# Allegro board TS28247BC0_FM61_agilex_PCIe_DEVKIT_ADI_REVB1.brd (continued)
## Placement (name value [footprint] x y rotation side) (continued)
C1846  470uF  [CAPMP7343X300L130X240N_P079IN]  165.74 35.46 180 top
C1847  470uF  [CAPMP7343X300L130X240N_P079IN]  174.87 62.18 0 top
C1848  1u  [CAPC1005X60L20L]  186.42 65.59 270 top
C1849  1u  [CAPC1005X60L20L]  186.52 75.97 270 top
C1850  22u  [CAPC3216X135L50N]  193.4 77.83 180 bottom
C1851  22u  [CAPC3216X135L50N]  193.4 77.83 180 top
C1852  22u  [CAPC3216X135L50N]  185.66 64.04 0 top
C1853  22u  [CAPC3216X135L50N]  185.68 64.04 0 bottom
C1856  470uF  [CAPMP7343X300L130X240N_P079IN]  165.49 69.29 180 top
C1857  100u  [CAPC2012X110L50L]  175.52 70.39 90 bottom
C1858  100u  [CAPC2012X110L50L]  175.52 68.38 90 bottom
C1859  1u  [CAPC1005X60L20L]  186.49 60.3 270 top
C1860  1u  [CAPC1005X60L20L]  186.47 49.91 270 top
C1861  22u  [CAPC3216X135L50N]  185.66 61.85 0 bottom
C1862  22u  [CAPC3216X135L50N]  185.66 61.85 0 top
C1863  22u  [CAPC3216X135L50N]  185.76 48.19 0 top
C1864  22u  [CAPC3216X135L50N]  185.76 48.19 0 bottom
C1867  22uF  [1206]  197.29 46.31 180 bottom
C1868  0.1uF  [0402]  196.1 49.61 180 top
C1869  470uF  [CAPMP7343X300L130X240N_P079IN]  165.49 54.87 180 top
C1870  100u  [CAPC2012X110L50L]  175.52 55.96 90 bottom
C1871  100u  [CAPC2012X110L50L]  175.52 53.95 90 bottom
C1872  22uF  [1206]  194.29 50.62 90 bottom
C1873  1uF  [0402]  198.64 51.13 45 top
C1874  10nF  [0402]  196.48 51.51 90 top
C1875  1u  [CAPC1005X60L20L]  186.67 33.76 270 top
C1876  1u  [CAPC1005X60L20L]  186.57 44.12 270 top
C1877  22u  [CAPC3216X135L50N]  185.81 45.54 0 bottom
C1878  22u  [CAPC3216X135L50N]  185.81 45.7 0 top
C1879  22u  [CAPC3216X135L50N]  191.55 34.09 180 top
C1880  22u  [CAPC3216X135L50N]  191.55 33.91 180 bottom
C1883  470uF  [CAPMP7343X300L130X240N_P079IN]  165.74 40.26 180 top
C1884  100u  [CAPC2012X110L50L]  175.52 40.92 90 bottom
C1885  100u  [CAPC2012X110L50L]  175.52 38.92 90 bottom
C1886  470uF  [D2E]  217.3 48.34 90 top
C1887  100uF  [1206]  215.88 48.47 270 bottom
C1888  100uF  [1206]  218.07 48.47 270 bottom
C1889  100uF  [1206]  220.25 48.47 270 bottom
C1890  220 uF  [CT7361-20]  218.14 57.43 270 bottom
C1891  22uF  [1206]  227.21 61.17 0 bottom
C1892  22uF  [1206]  227.21 61.17 0 top
C1893  22uF  [1206]  234.45 61.04 180 bottom
C1894  22uF  [1206]  234.45 61.17 180 top
C1895  1uF  [0402]  229.01 56.92 0 bottom
C1896  100uF  [1206]  237.5 42.75 90 bottom
C1897  100uF  [1206]  239.68 42.75 90 bottom
C1898  100uF  [1206]  241.87 42.75 90 bottom
C1899  470uF  [D2E]  241.82 42.37 270 top
C1900  1uF  [0402]  211.18 58.3 0 bottom
C1901  1uF  [0402]  209.3 61.8 270 bottom
C1902  22pF  [0402]  205.47 55.68 270 bottom
C1903  22uF  [1206]  209.96 63.48 0 top
C1904  10nF  [0402]  205.7 56.95 270 bottom
C1905  47uF  [C1206]  214.59 55.55 270 top
C1906  47uF  [C1206]  214.59 60.25 90 top
C1907  100uF  [1206]  64.9 64.09 180 top
C1908  22uF  [1206]  64.9 64.09 180 bottom
C1909  100pF  [0402]  72.42 71.55 90 bottom
C1910  22uF  [0603]  72.85 73.92 0 bottom
C1911  22uF  [0603]  76.89 70.31 180 bottom
C1912  47uF  [1206]  72.65 77.55 180 top
C1913  100uF  [1206]  72.65 77.55 0 bottom
C1914  0.1uF,DNI  [0402]  232.29 75.64 0 bottom
C1915  100uF  [1206]  219.84 81.99 0 top
C1916  100uF  [1206]  226.07 81.99 180 bottom
C1917  100uF  [1206]  219.84 81.99 0 bottom
C1918  150uF  [7343P]  236.91 81.16 90 bottom
C1919  22uF  [1206]  236.86 68.25 180 bottom
C1920  22uF  [1206]  236.86 68.3 180 top
C1921  22uF  [1206]  236.86 65.99 180 bottom
C1922  22uF  [1206]  236.86 66.12 180 top
C1923  22uF  [1206]  236.86 63.76 180 bottom
C1924  22uF  [1206]  236.86 63.83 180 top
C1925  10uF  [1206]  236.86 70.51 180 bottom
C1926  100uF,DNI  [1206]  224.8 78.18 180 bottom
C1928  470uF  [2917]  230.26 85.55 0 top
C1929  470uF  [2917]  220.73 85.55 180 top
C1930  100uF  [1206]  220.99 63.35 0 bottom
C1931  100uF  [1206]  225.69 63.35 180 bottom
C1932  100uF  [1206]  226.07 81.99 180 top
C1933  0.1uF,DNI  [0402]  219.08 78.82 90 bottom
C1934  2.2uF  [0402]  225.31 69.98 270 bottom
C1935  1500pF  [0402]  222.54 74.73 225 bottom
C1940  150pF  [0402]  221.57 73.23 180 bottom
C1941  100uF  [1206]  61.68 58.78 270 bottom
C1942  22uF  [1206]  63.15 52.05 180 bottom
C1943  100pF  [0402]  72.12 57.74 90 bottom
C1944  22uF  [0603]  72.8 60.07 0 bottom
C1945  22uF  [0603]  76.87 56.47 180 bottom
C1946  47uF  [1206]  72.78 63.96 180 bottom
C1947  100uF  [1206]  72.78 63.96 0 top
C1948  22uF  [1206]  197.62 83.01 270 bottom
C1949  22uF  [1206]  197.62 83.01 270 top
C1950  1u  [CAPC1005X60L20L]  201.43 83.9 90 bottom
C1951  2.2uF  [CC0603N]  212.99 80.09 0 bottom
C1952  100uF  [1206]  199.85 76.99 0 bottom
C1953  100uF  [1206]  204.68 76.99 180 bottom
C1954  100uF  [1206]  212.73 76.91 180 top
C1956  0.1uF,DNI  [0402]  203.66 86.13 45 bottom
C1957  0.1uF  [0402]  200.79 85.8 0 bottom
C1958  22uF  [1206]  196.22 40.36 270 bottom
C1959  22uF  [1206]  195.82 37.24 90 top
C1960  1u  [CAPC1005X60L20L]  199.78 41.2 90 bottom
C1961  2.2uF  [CC0603N]  197.62 36.15 180 bottom
C1962  100uF  [1206]  199.14 34.11 0 top
C1963  100uF  [1206]  208.92 34.14 0 top
C1964  100uF  [1206]  203.94 34.11 180 top
C1966  0.1uF,DNI  [0402]  206.41 46.56 0 bottom
C1967  0.1uF  [0402]  198.64 43.77 270 bottom
C1975  1uF  [0402]  210.65 70.44 180 top
C1976  1uF  [0402]  212.94 71.53 225 top
C1977  22uF  [1206]  212 74.58 180 bottom
C1978  22pF  [0402]  215.2 65.28 180 top
C1979  10nF  [0402]  215.78 67.39 180 top
C1980  47uF  [C1206]  205.84 68.23 180 bottom
C1981  47uF  [C1206]  205.84 66.04 180 bottom
C1986  22uF  [1206]  70.62 43.89 180 top
C1987  1u  [CAPC1005X60L20L]  68.66 36.73 90 bottom
C1988  47uF  [C1206]  64.09 35.74 270 top
C1989  47uF  [C1206]  74.76 42.52 90 top
C1990  1uF  [0402]  54.13 54.28 90 top
C1991  22uF  [1206]  48.6 55.43 0 bottom
C1992  47uF  [C1206]  49.84 59.11 90 bottom
C1993  47uF  [C1206]  48.62 52.98 0 bottom
C1994  1uF  [0402]  190.58 69.9 180 bottom
C1995  10uF  [0402]  188.75 69.04 0 bottom
C1996  1uF  [0402]  190.45 54.89 180 bottom
C1997  10uF  [0402]  188.53 54.46 0 bottom
C1998  1uF  [0402]  190.43 38.61 180 bottom
C1999  10uF  [0402]  188.5 38.28 0 bottom
C2000  22uF  [1206]  209.96 63.48 0 bottom
C2001  22uF  [1206]  212 74.58 180 top
C2002  1uF  [0402]  236.61 59.13 180 bottom
C2003  DNI  [0402]  231.55 52.63 0 bottom
C2004  360pF  [0402]  232.85 53.65 90 bottom
C2007  0.47uF  [0402]  192.84 63.63 270 bottom
C2008  0.47uF  [0402]  197.17 66.59 180 bottom
C2009  0.47uF  [0402]  192.86 64.54 270 bottom
C2010  0.47uF  [0402]  195.47 66.51 180 bottom
C2011  22u  [CAPC3216X135L50N]  200.34 68.46 0 bottom
C2012  0.1uF,DNI  [0402]  195.43 59.87 180 bottom
C2013  100u  [CAPC2012X110L50L]  175.52 86.62 90 bottom
C2014  100u  [CAPC2012X110L50L]  175.52 80.34 90 bottom
C2015  100u  [CAPC2012X110L50L]  175.52 66.37 90 bottom
C2016  100u  [CAPC2012X110L50L]  175.52 72.39 90 bottom
C2017  47pF  [0402]  189.5 80.1 0 bottom
C2018  47pF  [0402]  188.65 87.99 0 bottom
C2019  47pF  [0402]  190.1 74.7 270 bottom
C2020  47pF  [0402]  189.47 65.94 0 bottom
C2021  100u  [CAPC2012X110L50L]  175.52 57.86 90 bottom
C2022  100u  [CAPC2012X110L50L]  175.52 52.02 90 bottom
C2023  100u  [CAPC2012X110L50L]  175.52 36.91 90 bottom
C2024  100u  [CAPC2012X110L50L]  175.52 42.93 90 bottom
C2025  47pF  [0402]  188.65 59.79 0 bottom
C2026  47pF  [0402]  189.24 50.42 0 bottom
C2027  47pF  [0402]  188.5 43.49 0 bottom
C2028  47pF  [0402]  190.1 36.73 90 bottom
C2029  22uF  [1206]  192.01 46.38 0 bottom
C2030  22uF  [1206]  205.06 49.99 90 bottom
C2031  100pF,DNI  [0402]  196.54 52.78 270 top
C2032  100pF,DNI  [0402]  209.02 54.94 270 bottom
C2033  100pF,DNI  [0402]  212.71 65.28 180 top
C2034  100pF  [0402]  64.19 43.79 90 bottom
C2035  22uF  [1206]  68.76 34.45 0 top
C2036  100pF  [0402]  59.14 56.54 0 top
C2037  22uF  [1206]  48.6 55.43 0 top
C2038  4.7uF  [0402]  52.48 54.74 45 top
C2039  4.7uF  [0402]  71.1 40.39 225 bottom
C7761  0.1uF  [0402]  230.82 19.64 0 top
C7762  100pF  [0402]  230.21 18.29 270 top
C7763  10pF  [0603]  228.45 18.82 90 top
C7764  47pF  [0402]  230.54 22.05 0 bottom
C7765  0.1uF  [0402]  234.6 24.31 90 bottom
C7766  10uF  [0402]  229.19 24.41 270 bottom
C7767  10uF  [0805]  226.17 26.14 0 top
C7768  4.7uF  [0603]  227.95 26.19 270 top
C7769  10uF  [0805]  237.4 26.55 0 top
C7770  4.7uF  [0603]  235.49 26.34 270 top
C7771  330uF  [7343P]  242.7 35.13 0 top
C7772  330uF  [7343P]  219.54 34.01 180 top
C7773  100uF  [0805]  225.89 31.12 0 top
C7774  100uF  [0805]  237.88 30.81 0 top
C7775  47uF  [0603]  227.9 31.22 270 top
C7776  47uF  [0603]  236.1 31.22 270 top
C7777  0.1uF  [0402]  229.5 39.45 180 top
C7778  0.1uF  [0402]  229.5 37.54 180 top
C7779  220 uF  [CT7361-20]  243.11 26.14 90 top
D2  GREEN_LED  [LED_0603]  14.99 102.44 0 top
D3  GREEN_LED  [LED_0603]  18.42 102.44 0 top
D4  ESD5V3U2U  [TSLP-3-7]  38.74 99.77 90 bottom
D5  ESD5V3U2U  [TSLP-3-7]  38.74 94.69 90 bottom
D6  ESD5V3U2U  [TSLP-3-7]  38.74 97.11 90 bottom
D7  GREEN_LED  [LED_0603]  270.39 35.13 0 top
D8  BLUE LED  [LED_0603]  270.39 36.65 0 top
D9  GREEN_LED  [LED_0603]  270.39 38.18 0 top
D10  GREEN_LED  [LED_0603]  270.39 39.7 0 top
D11  RED_LED  [LED_0603]  270.39 41.23 0 top
D12  GREEN_LED  [LED_0603]  270.39 42.75 0 top
D13  GREEN_LED  [LED_0603]  270.39 44.27 0 top
D14  GREEN_LED  [LED_0603]  270.39 45.8 0 top
D15  5p0SMDJ12A  [TVS_5P0SMDJ12A]  255.63 104.75 0 bottom
D16  5p0SMDJ12A  [TVS_5P0SMDJ12A]  258.33 72.47 90 bottom
D21  GREEN_LED  [LED_0603]  2.42 55.93 270 top
D22  APHB1608CGKSYKC  [LED0603_4PIN_APHB1608]  6.45 55.7 270 top
D23  GREEN_LED  [LED_0603]  10.45 55.7 270 top
D24  APHB1608CGKSYKC  [LED0603_4PIN_APHB1608]  14.45 55.7 270 top
D25  PMEG2005AEL,315  [DIO_SOD882]  227.51 45.27 180 top
FB9  80ohm @ 100Mhz  [0805]  142.03 37.33 90 top
FB10  80ohm @ 100Mhz  [0805]  85.3 71.43 0 top
FB11  80ohm @ 100Mhz  [0805]  148.13 76.83 270 top
FB12  DNI  [0402]  129.21 54.15 240 bottom
FB13  220ohm  [0402]  127.42 54.65 120 bottom
FB14  220ohm  [0402]  144.63 62.43 0 bottom
FB15  220ohm  [0402]  130.02 51.71 60 bottom
FB16  80ohm @ 100Mhz  [0805]  80.3 55.5 0 bottom
FB17  22ohm@100Mhz 8A  [0603]  154.06 76.41 90 bottom
FB18  22ohm@100Mhz 8A  [0603]  152.15 76.41 90 bottom
FB19  220ohm  [0402]  47.89 30.69 90 bottom
FB20  220ohm  [0402]  47.25 21.03 180 bottom
FB21  220ohm  [0402]  43.06 23.7 270 bottom
FB22  220ohm  [0402]  54.24 20.4 180 bottom
FB23  220ohm  [0402]  207.91 103.96 0 bottom
FB24  220ohm  [0402]  40.14 47.01 180 bottom
FB25  600 Ohm, 0.5A, 0.35DCR  [0603]  8.14 19.38 270 top
FB26  600 Ohm, 0.5A, 0.35DCR  [0603]  25.87 19.7 90 bottom
FB27  600 Ohm, 0.5A, 0.35DCR  [0603]  33.03 17.6 0 bottom
FB28  600 Ohm, 0.5A, 0.35DCR  [0603]  24.65 28.53 90 bottom
FB29  220ohm, 2.0A  [0805]  254.64 19.51 90 bottom
FB30  80ohm @ 100Mhz  [0805]  250.32 42.37 180 bottom
FB31  80ohm @ 100Mhz  [0805]  28.96 45.67 270 bottom
FB33  80ohm @ 100Mhz  [0805]  213.85 51.41 180 top
FB36  80ohm @ 100Mhz  [0805]  20.71 45.67 270 bottom
FB37  80ohm @ 100Mhz  [0805]  147.11 59.6 90 bottom
FB38  80ohm @ 100Mhz  [0805]  148.13 79.03 90 top
FB40  220ohm  [0402]  205.92 100.15 0 top
FB41  220ohm  [0402]  204.6 106.25 180 bottom
FB42  220ohm  [0402]  203.72 98.07 180 top
FB45  220ohm  [0402]  128.4 50.24 90 bottom
HW1  -  [LIGHTPIPE_P-U90-1101-T00A-BP]  12.45 56.75 270 top
J1  DDR4x72x288  [DDR4DIMM_SMT]  129.52 94.44 0 top
J2  DDR4x72x288  [DDR4DIMM_SMT]  129.52 102.06 0 top
J3  DDR4x72x288  [DDR4DIMM_SMT]  129.52 29.42 180 top
J4  DDR4x72x288  [DDR4DIMM_SMT]  129.52 21.8 180 top
J5  -  [2027180100]  46.1 68.09 0 top
J6  -  [2027180100]  46.1 43.3 0 top
J7  PCIE_Slot  [PCIX-16PORT]  45.66 3.56 0 top
J8  ENET_L829-1J1T-43  [BEL_L829-1J1T-43]  18.13 84.64 270 top
J9  CON2  [HDR2X1_100MIL]  21.98 22.05 270 top
J10  MICRO_USB_CONN  [MOLEX-MICRO-USB-47589-001]  17.91 109.7 0 top
J11  MicroSD_skt  [WURTH_MICRO-SD_CARD]  32.57 98.8 270 top
J12  Mictor38P  [SMT38]  48.01 84.74 0 top
J13  MICRO_USB_CONN  [MOLEX-MICRO-USB-47589-001]  1.45 25.76 90 top
J14  0702461004  [MOLEX_0702461004]  223.15 99.39 0 top
J15  FAN_Conn  [MOLEX_0470533000]  268.49 24.46 270 top
J16  PCIe 2x4 ATX  [MLX_SD-5569_8POS_RA]  260.34 96.27 270 top
J17  TSW-103-08-G-S  [1X3_HDR_TH]  236.48 89.36 180 top
J22  95278-101A04LF  [AMPHENOL_95278-X01X04LF]  217.15 20.91 90 top
L1  742792780  [0402]  16.26 98.45 180 bottom
L2  742792780  [0402]  17.41 98.45 180 bottom
L3  3A, 30 Ohm FB  [IND_0603]  36.58 82.63 90 bottom
L4  3A, 30 Ohm FB  [IND_0603]  17.03 76.91 90 bottom
L5  3A, 30 Ohm FB  [IND_0603]  16.26 80.85 90 bottom
L6  3A, 30 Ohm FB  [IND_0603]  25.53 90.12 0 top
L7  3A, 30 Ohm FB  [IND_0603]  39.63 82.63 90 bottom
L8  742792780  [0402]  19.95 104.6 180 top
L9  BLM15AG221SN1  [0402]  262.29 30.81 0 bottom
L14  65nH  [SL1616A-R06LU]  69.73 48.34 0 top
L15  1uH  [IFSC1008ABER1R0M01]  46.74 65.86 0 bottom
L16  1uH  [IFSC1008ABER1R0M01]  46.74 72.09 0 bottom
L17  1uH  [IFSC1008ABER1R0M01]  46.74 75.01 0 bottom
L18  1uH  [IFSC1008ABER1R0M01]  46.74 41.1 0 bottom
L19  1uH  [IFSC1008ABER1R0M01]  46.74 47.2 0 bottom
L20  1uH  [IFSC1008ABER1R0M01]  46.74 50.24 0 bottom
L23  150 nH  [IND_FP1008R-CUS]  177.17 83.39 180 top
L24  150 nH  [IND_FP1008R-CUS]  177.17 69.67 180 top
L25  150 nH  [IND_FP1008R-CUS]  177.17 55.2 180 top
L26  150 nH  [IND_FP1008R-CUS]  177.17 39.02 180 top
L30  0.35 uH  [IND_XGL5030]  231.99 31.12 90 top
MTH1  MT_HOLE_GND  [MH_D125C175T_TB315]  269.33 16.65 0 top
MTH2  MT_HOLE_GND  [MH_D125C175T_TB315]  7.5 104.65 180 bottom
MTH3  MT_HOLE_GND  [MT_HOLE]  36.33 108.09 0 top
MTH4  MT_HOLE_GND  [MH_D125C175T_TB315]  269.35 106.14 0 top
MTH5  MT_HOLE_GND  [MH_D125C175T_TB315]  7.5 9.35 180 bottom
MTH6  MT_HOLE_GND  [MT_HOLE]  20 15.8 0 top
NOREF  -  []  58.29 0.31 0 top
NOREF#2  -  []  196.64 65.04 0 top
NOREF#3  -  [unnamed#2]  150.5 39.07 0 top
NOREF#4  -  [unnamed#3]  81.08 14.82 0 top
NOREF#5  -  []  143.35 2.95 0 top
NOREF#6  -  []  68.16 53.29 0 top
NOREF#7  -  []  229.25 28.48 90 top
NOREF#8  -  []  139.03 11 0 top
NOREF#9  -  []  0 4.5 0 top
NOREF#10  -  []  215.25 16.91 90 top
NOREF#11  -  [unnamed#2]  70.8 108.09 0 top
NOREF#12  -  []  7.5 94.75 0 top
NOREF#13  -  []  188.6 66.74 90 top
NOREF#14  -  []  197.99 36.73 90 top
NOREF#15  -  []  15 12.75 0 top
NOREF#16  -  []  41.35 10.92 0 top
NOREF#17  -  []  217.36 47.87 90 top
NOREF#18  -  [unnamed#2]  96.2 15.8 0 top
NOREF#19  -  []  7.5 94.75 0 top
NOREF#20  -  []  236.02 78.43 0 top
NOREF#21  -  []  232.75 37.2 0 top
NOREF#22  -  [unnamed#2]  262.64 105.23 0 top
NOREF#23  -  [unnamed#2]  70.8 15.8 0 top
NOREF#24  -  []  183.6 43.02 0 top
NOREF#25  -  [unnamed#4]  57.03 18.87 0 top
NOREF#26  -  []  199.64 88.4 0 top
NOREF#27  -  [unnamed#2]  86.72 14.91 0 top
NOREF#28  -  []  45.5 0 0 top
NOREF#29  -  []  41.35 10.92 0 top
NOREF#30  -  []  45 0.5 0 top
NOREF#31  -  [unnamed#2]  213.04 15.75 0 top
NOREF#32  -  []  61.95 75.42 0 top
NOREF#33  -  [unnamed#2]  193.36 108.09 0 top
NOREF#34  -  []  183.7 86.39 90 top
NOREF#35  -  []  196.64 57.04 90 top
NOREF#36  -  []  33.35 4.5 0 top
NOREF#37  -  []  56.2 0.5 0 top
NOREF#38  -  [unnamed#2]  81.92 84.79 0 top
NOREF#39  -  []  188.6 35.02 90 top
NOREF#40  -  []  214.42 19.64 90 top
NOREF#41  -  [unnamed#2]  99.63 108.09 0 top
NOREF#42  -  []  0 111.15 0 top
NOREF#43  -  []  188.6 79.39 90 top
NOREF#44  -  []  240.06 22.49 90 top
NOREF#45  -  []  76.95 66.42 90 top
NOREF#46  -  []  7.5 9.35 0 top
NOREF#47  -  []  222.26 47.09 0 top
NOREF#48  -  []  183.7 58.2 90 top
NOREF#49  -  []  351.78 376.9 0 top
NOREF#50  -  []  234.68 38.44 90 top
NOREF#51  -  []  200.79 80.09 0 top
NOREF#52  -  [unnamed#2]  75.46 14.81 0 top
NOREF#53  -  [unnamed#3]  81.08 14.82 0 top
NOREF#54  -  []  44.45 9.62 0 top
NOREF#55  -  []  7.5 9.35 0 top
NOREF#56  -  [unnamed#2]  65.52 14.66 0 top
NOREF#57  -  []  218.07 105.11 0 top
NOREF#58  -  []  215.09 53.78 90 top
NOREF#59  -  []  214.74 18.44 90 top
NOREF#60  -  []  63.1 67.11 90 top
NOREF#61  -  []  201.36 79.87 0 top
NOREF#62  -  []  7.5 94.75 0 top
NOREF#63  -  []  7.5 9.35 0 top
NOREF#64  -  []  199.14 37.42 0 top
NOREF#65  -  []  231.08 64.88 0 top
NOREF#66  -  [unnamed#4]  24.65 18.87 0 top
NOREF#67  -  []  201.56 63.84 90 top
NOREF#68  -  []  0.01 123.85 0 top
NOREF#69  -  []  238.39 96.22 90 top
NOREF#70  -  [unnamed#2]  86.72 14.91 0 top
NOREF#71  -  []  63.08 53.29 90 top
NOREF#72  -  []  7.5 104.88 0 top
NOREF#73  -  [unnamed#4]  6.23 30.94 0 top
NOREF#74  -  [unnamed#2]  75.46 14.81 0 top
NOREF#75  -  []  240.06 29.79 0 top
NOREF#76  -  []  202.06 48.97 90 top
NOREF#77  -  [unnamed#2]  192.09 15.8 0 top
NOREF#78  -  []  183.6 74.74 0 top
NOREF#79  -  []  -309.9 -46.1 0 top
NOREF#80  -  [unnamed#2]  262.14 18.24 0 top
NOREF#81  -  [unnamed#2]  4.96 18.87 0 top
NOREF#82  -  [unnamed#2]  247.97 108.09 0 top
NOREF#83  -  []  15 4.5 0 top
NOREF#84  -  []  223.27 58.12 0 top
NOREF#85  -  []  144.74 5.32 0 top
NOREF#86  -  []  61.93 61.6 0 top
NOREF#87  -  [unnamed#2]  213.95 108.09 0 top
NOREF#88  -  []  132.04 3.45 0 top
NOREF#89  -  [unnamed#4]  39.25 30.94 0 top
NOREF#90  -  []  237.95 70.83 90 top
NOREF#91  -  []  222.26 47.09 90 top
NOREF#92  -  []  183.6 59.2 0 top
NOREF#93  -  [unnamed#3]  67.49 86.14 0 top
NOREF#94  -  []  183.6 87.39 0 top
NOREF#95  -  []  223.15 99.39 90 top
NOREF#96  -  []  367.14 376.9 0 top
NOREF#97  -  []  229.25 33.76 0 top
NOREF#98  -  []  210.02 23.27 0 top
NOREF#99  -  []  0 4.5 0 top
NOREF#100  -  [unnamed#2]  150.5 84.79 0 top
NOREF#101  -  [unnamed#2]  81.92 39.07 0 top
NOREF#102  -  []  197.99 45.73 0 top
NOREF#103  -  []  129.3 0.5 0 top
NOREF#104  -  []  196.4 48.39 90 top
NOREF#105  -  []  60.08 -68.63 0 top
NOREF#106  -  []  183.7 42.02 90 top
NOREF#107  -  []  76.93 52.6 90 top
NOREF#108  -  []  188.6 51.2 90 top
NOREF#109  -  []  199.64 79.4 90 top
NOREF#110  -  []  231.99 29.46 90 top
NOREF#111  -  []  147.3 10.21 0 top
NOREF#112  -  []  7.5 104.88 0 top
NOREF#113  -  [unnamed#2]  65.52 14.66 0 top
NOREF#114  -  [unnamed#2]  41.08 15.8 0 top
NOREF#115  -  []  215.09 53.78 0 top
NOREF#116  -  [unnamed#4]  247.81 19.08 0 top
NOREF#117  -  [unnamed#3]  67.49 86.14 0 top
NOREF#118  -  [unnamed#2]  128.59 108.09 0 top
NOREF#119  -  [unnamed#2]  247.97 15.75 0 top
NOREF#120  -  [unnamed#2]  169.23 15.8 0 top
NOREF#121  -  []  58.1 0.5 0 top
NOREF#122  -  []  7.75 113.69 0 top
NOREF#123  -  []  200.79 54.05 0 top
NOREF#124  -  [unnamed#4]  264.68 33.48 0 top
NOREF#125  -  []  68.18 67.11 0 top
NOREF#126  -  []  56.2 7.45 0 top
NOREF#127  -  []  196.4 48.39 0 top
NOREF#128  -  []  183.7 73.74 90 top
NOREF#129  -  [unnamed#4]  210.07 24.59 0 top
NOREF#130  -  [unnamed#2]  4.96 18.87 180 bottom
NOREF#131  -  [unnamed#2]  262.14 18.24 180 bottom
NOREF#132  -  [unnamed#2]  269.81 99.67 180 bottom
Q1  FDV305N  [SOT23]  15.18 101.5 0 bottom
Q2  FDV305N  [SOT23]  6.92 91.73 90 bottom
Q3  FDV305N  [SOT23]  18.99 101.5 0 bottom
Q4  FDV305N  [SOT23]  6.92 87.92 90 bottom
Q5  FDV305N  [SOT23]  261.37 39.07 90 bottom
Q6  FDV305N  [SOT23]  265.82 39.07 90 bottom
Q7  FDV305N  [SOT23]  265.82 43.13 90 bottom
Q8  FDV305N  [SOT23]  261.37 43.13 90 bottom
Q9  FDV305N  [SOT23]  266.07 47.96 0 bottom
Q10  FDV305N  [SOT23]  270.14 52.53 0 bottom
Q11  FDV305N  [SOT23]  270.14 47.96 0 bottom
Q12  PSMN1R0-30YLD  [NFET_PSMN1R0-30YLD]  250.3 87.28 180 top
Q13  SI2302CDS-T1-GE3  [SOT23]  241.31 80.85 0 bottom
Q24  FDV305N  [SOT23]  17.41 63.32 0 bottom
Q25  FDV305N  [SOT23]  21.09 63.32 0 bottom
Q26  FDV305N  [SOT23]  24.77 63.32 0 bottom
Q27  FDV305N  [SOT23]  29.47 58.88 0 bottom
Q28  FDV305N  [SOT23]  28.46 63.32 0 bottom
Q29  FDV305N  [SOT23]  32.27 63.32 0 bottom
R1  0  [1206]  67.32 95.71 180 bottom
R2  0  [1206]  67.32 93.17 180 bottom
R3  10.0K,DNI  [0402]  144.03 97.41 270 bottom
R4  10.0K  [0402]  139.45 93.04 0 bottom
R5  10.0K  [0402]  190.76 91.44 270 bottom
R6  10.0K  [0402]  190.76 97.44 270 bottom
R7  0  [0402]  189.64 92.52 90 bottom
R8  0  [0402]  188.96 91.44 270 bottom
R9  0  [0402]  150.79 98.07 90 bottom
R10  10.0K  [0402]  114.94 93.17 270 bottom
R11  DNI  [0402]  114.24 92.08 270 bottom
R12  DNI  [0402]  116.34 93.04 180 bottom
R13  DNI  [0402]  115.07 97.49 270 bottom
R14  0  [0603]  192.92 96.85 90 bottom
R15  240  [0402]  124.42 73.33 0 bottom
R16  DNI  [0402]  125.31 83.93 0 bottom
R17  0  [1206]  67.32 103.2 180 bottom
R18  0  [1206]  67.32 100.79 180 bottom
R19  0  [0603]  99.32 101.68 180 bottom
R20  DNI  [0603]  99.32 103.46 180 bottom
R21  DNI  [0402]  143.06 105.06 90 bottom
R22  10.0K  [0402]  139.45 100.66 0 bottom
R23  10.0K  [0402]  189.64 100.14 270 bottom
R24  0  [0402]  188.96 99.06 270 bottom
R25  0  [0402]  152.28 103.08 90 bottom
R26  10.0K  [0402]  115.08 100.15 270 bottom
R27  DNI  [0402]  114.24 99.06 270 bottom
R28  DNI  [0402]  116.87 99.06 90 bottom
R29  DNI  [0402]  115.07 105.11 270 bottom
R30  0  [0603]  192.92 103.96 90 bottom
R31  100  [0402]  85.8 77.43 0 top
R32  10.0K  [0402]  116.65 83.98 180 bottom
R33  10.0K  [0402]  118.38 83.98 180 bottom
R34  10.0K  [0402]  115.78 83.98 180 bottom
R35  10.0K  [0402]  117.51 83.98 180 bottom
R36  10.0K  [0402]  108.85 83.98 0 bottom
R37  10.0K  [0402]  107.99 83.98 0 bottom
R38  10.0K  [0402]  120.98 83.98 0 bottom
R39  10.0K  [0402]  110.58 83.98 0 bottom
R40  10.0K  [0402]  109.72 83.98 0 bottom
R41  10.0K  [0402]  111.45 83.98 0 bottom
R42  10.0K,DNI  [0402]  120.11 83.98 0 bottom
R43  10.0K,DNI  [0402]  119.24 83.98 180 bottom
R44  10.0K,DNI  [0402]  112.32 83.98 0 bottom
R45  10.0K,DNI  [0402]  113.18 83.98 180 bottom
R46  4.7K  [0402]  114.91 83.98 0 bottom
R47  4.7K  [0402]  114.05 83.98 0 bottom
R48  240  [0402]  101.42 72.8 90 bottom
R49  10.0K  [0402]  106.25 83.98 180 bottom
R50  10.0K  [0402]  107.12 83.98 180 bottom
R53  DNI  [0402]  87.3 75.93 90 bottom
R54  0  [1206]  191.78 30.69 0 bottom
R55  0  [1206]  191.78 28.4 0 bottom
R56  10.0K,DNI  [0402]  119.64 30.91 180 bottom
R57  10.0K  [0402]  115.9 26.42 270 bottom
R58  0  [0402]  70.49 31.83 180 bottom
R59  10.0K  [0402]  69.53 31.83 180 bottom
R60  0  [0402]  108.25 25.78 270 bottom
R61  10.0K  [0402]  143.95 31.4 90 bottom
R62  DNI  [0402]  144.8 32.36 90 bottom
R63  DNI  [0402]  142.29 32.36 270 bottom
R64  DNI  [0402]  143.97 26.37 90 bottom
R65  0  [0603]  66.11 27 270 bottom
R66  240  [0402]  121.42 50.04 270 bottom
R67  DNI  [0402]  123.57 39.93 180 bottom
R68  0  [1206]  191.72 22.91 0 bottom
R69  0  [1206]  191.72 20.5 0 bottom
R70  10.0K,DNI  [0402]  122.37 25.29 0 bottom
R71  10.0K  [0402]  115.9 18.8 270 bottom
R72  10.0K  [0402]  70.49 23.19 180 bottom
R73  10.0K  [0402]  69.53 24.21 180 bottom
R74  0  [0402]  108.25 18.03 270 bottom
R75  10.0K  [0402]  143.95 23.78 90 bottom
R76  DNI  [0402]  144.8 24.74 90 bottom
R77  DNI  [0402]  142.29 24.74 270 bottom
R78  DNI  [0402]  143.97 18.75 90 bottom
R79  0  [0603]  66.11 19.38 270 bottom
R80  100  [0402]  107.99 39.93 0 bottom
R81  10.0K  [0402]  104.52 39.87 180 bottom
R82  10.0K  [0402]  103.66 39.87 180 bottom
R83  10.0K  [0402]  102.79 39.87 180 bottom
R84  240  [0402]  95.1 39.96 180 bottom
R85  DNI  [0402]  96.73 39.93 180 bottom
R86  2K  [0402]  105.87 66.21 120 bottom
R87  169,0.1%  [0402]  131.37 59.43 180 bottom
R88  2.8K  [0402]  126.03 57.43 180 bottom
R89  10.0K  [0402]  131.58 54.56 180 bottom
R90  10.0K  [0402]  45.85 62.69 270 bottom
R91  10.0K  [0402]  43.95 62.69 270 bottom
R92  4.7K  [0402]  43.95 63.71 90 bottom
R93  4.7K  [0402]  45.85 63.71 90 bottom
R94  1M  [0402]  21.6 57.86 0 bottom
R95  10.0K  [0402]  45.93 39.17 270 bottom
R96  10.0K  [0402]  45.93 38.18 270 bottom
R97  1M  [0402]  26.17 53.55 180 bottom
R98  4.7K  [0402]  49.92 11 180 top
R99  4.7K  [0402]  50.93 11 180 top
R100  DNI  [0402]  54.24 10.62 90 bottom
R101  DNI  [0402]  54.74 11 180 top
R102  4.7K  [0402]  51.7 11 0 bottom
R103  4.7K  [0402]  52.71 11 0 bottom
R104  10.0K  [0402]  53.73 11 0 top
R105  10.0K  [0402]  55.63 11 0 bottom
R106  10.0K  [0402]  54.24 11.51 270 bottom
R107  10.0K  [0402]  215.4 25.61 180 bottom
R108  10.0K  [0402]  214.13 25.61 180 bottom
R109  10.0K  [0402]  212.86 25.61 180 bottom
R110  1K  [0402]  216.42 37.04 90 bottom
R111  1K  [0402]  214.64 37.04 90 bottom
R112  1K  [0402]  212.86 37.04 270 bottom
R113  33  [0402]  154.1 53.45 90 bottom
R114  2K  [0402]  133.1 52.43 180 bottom
R115  1K  [0402]  208.01 32.09 180 bottom
R116  240  [0402]  203.33 26.3 0 bottom
R117  10.0K  [0402]  136.81 40.31 0 bottom
R118  10.0K  [0402]  137.7 40.31 0 bottom
R119  1K  [0402]  146.23 47.33 90 bottom
R120  10.0K  [0402]  135.04 40.31 0 bottom
R121  10.0K  [0402]  131.48 40.31 0 bottom
R122  10.0K  [0402]  134.15 40.31 0 bottom
R123  10.0K  [0402]  135.92 40.31 0 bottom
R124  10.0K  [0402]  137.68 36.27 180 bottom
R125  10.0K  [0402]  133.26 40.31 0 bottom
R126  220  [0402]  2.93 89.36 90 bottom
R127  33  [0402]  25.5 81.27 0 top
R128  0  [0402]  33.54 81.1 180 bottom
R129  33  [0402]  25.5 81.12 180 bottom
R130  33  [0402]  29.95 81.27 0 top
R131  33  [0402]  29.95 81.12 180 bottom
R132  33  [0402]  24.77 78.5 90 bottom
R133  33  [0402]  32.61 81.12 180 bottom
R134  220  [0402]  2.93 90.25 90 bottom
R135  12.1K  [0402]  24.45 88.47 90 top
R136  DNI  [0402]  35.82 92.03 180 bottom
R137  4.7K  [0402]  34.93 92.03 0 bottom
R138  DNI  [0402]  36.84 80.6 90 bottom
R139  4.7K  [0402]  34.93 80.6 90 bottom
R140  1K  [0402]  10.29 90.25 90 bottom
R141  4.7K  [0402]  31.73 81.12 0 bottom
R142  DNI  [0402]  30.84 81.12 180 bottom
R143  1K  [0402]  10.29 89.23 90 bottom
R144  4.7K  [0402]  24.77 77.55 270 bottom
R145  DNI  [0402]  26.17 77.99 0 bottom
R146  4.7K  [0402]  29.06 81.12 0 bottom
R147  DNI  [0402]  28.17 81.12 180 bottom
R148  4.7K  [0402]  29.06 81.27 180 top
R149  DNI  [0402]  28.17 81.27 0 top
R150  DNI  [0402]  26.39 81.12 0 bottom
R151  4.7K  [0402]  27.28 81.12 180 bottom
R152  4.7K  [0402]  26.39 81.27 180 top
R153  DNI  [0402]  27.28 81.27 0 top
R154  4.7K  [0402]  24.11 84.16 180 top
R155  DNI  [0402]  23.98 86.2 180 top
R156  4.7K  [0402]  24.61 81.27 180 top
R157  4.7K  [0402]  24.59 81.1 0 bottom
R158  4.7K  [0402]  23.71 81.1 0 bottom
R159  4.7K  [0402]  22.82 81.1 0 bottom
R160  10.0K  [0402]  41.41 88.34 180 bottom
R161  75  [0402]  33.03 92.03 0 bottom
R162  0  [0402]  37.98 92.03 180 bottom
R163  4.7K  [0402]  56.52 94.69 180 bottom
R164  2.61K  [0402]  50.17 93.93 0 bottom
R165  4.7K  [0402]  49.28 95.71 180 bottom
R166  1.87K  [0402]  50.17 95.71 180 bottom
R167  10.0K  [0402]  22.87 66.37 90 bottom
R169  33  [0402]  28.84 67.64 90 bottom
R171  0  [0402]  26.04 73.23 270 bottom
R172  4.7K  [0402]  25.03 72.21 90 bottom
R173  0  [0402]  16.26 104.6 0 top
R174  10.0K  [0402]  31.12 74.5 0 bottom
R175  DNI  [0402]  26.55 71.45 0 bottom
R176  0  [0402]  15.12 104.6 0 bottom
R177  220  [0402]  25.03 69.04 270 bottom
R178  220  [0402]  25.03 70.06 270 bottom
R179  10.0K  [0402]  18.93 74.63 90 bottom
R180  200K  [0402]  49.79 97.23 270 bottom
R181  DNI  [0402]  41.41 90.63 0 bottom
R182  1K  [0402]  42.3 90.63 0 bottom
R183  1K  [0402]  45.85 90.63 0 bottom
R184  1K  [0402]  44.97 90.63 0 bottom
R185  1K  [0402]  44.08 90.63 0 bottom
R186  1K  [0402]  43.19 90.63 0 bottom
R187  0  [0402]  49.79 99.01 270 bottom
R188  0.1  [0805]  43.7 104.85 270 bottom
R189  499  [0603]  46.49 102.19 90 bottom
R190  4.7K  [0402]  46.74 108.54 270 bottom
R191  499  [0603]  45.09 102.19 90 bottom
R192  499  [0603]  43.7 102.19 90 bottom
R193  499  [0603]  41.16 102.19 90 bottom
R194  330  [0603]  39.76 102.19 90 bottom
R195  330  [0603]  38.36 102.19 90 bottom
R196  DNI  [0402]  42.43 101.68 180 bottom
R197  0  [0402]  50.93 90.12 180 bottom
R198  0  [0402]  50.05 90.12 180 bottom
R199  0  [0402]  49.16 90.12 180 bottom
R200  0  [0402]  48.27 90.12 180 bottom
R201  10.0K  [0402]  52.46 81.23 180 bottom
R202  10.0K  [0402]  51.82 88.22 180 bottom
R203  10.0K  [0402]  51.82 79.58 0 bottom
R204  10.0K,DNI  [0402]  50.68 81.61 270 bottom
R205  0  [0603]  50.55 79.56 270 bottom
R206  10.0K  [0402]  50.05 88.22 180 bottom
R207  DNI  [0603]  49.03 79.56 270 bottom
R208  10.0K  [0402]  45.47 81.61 90 bottom
R209  10.0K  [0402]  44.9 80.72 90 bottom
R210  10.0K  [0402]  43.57 81.1 0 bottom
R211  10.0K  [0402]  42.3 81.1 180 bottom
R212  10.0K  [0402]  52.71 90.12 0 bottom
R213  10.0K  [0402]  47.38 88.22 180 bottom
R214  1K  [0402]  48.27 88.22 0 bottom
R215  1K  [0402]  51.82 90.12 180 bottom
R216  1K  [0402]  49.16 88.22 0 bottom
R217  1K  [0402]  50.93 88.22 0 bottom
R218  33  [0402]  24.77 108.28 180 bottom
R219  33  [0402]  27.44 108.28 180 bottom
R220  33  [0402]  23.12 103.74 90 top
R221  33  [0402]  23.12 102.85 90 top
R222  33  [0402]  23.12 101.96 90 top
R223  33  [0402]  23.06 104.73 90 top
R224  33  [0402]  24.52 92.03 0 bottom
R225  33  [0402]  20.33 98.9 270 bottom
R226  33  [0402]  32.39 108.28 180 bottom
R227  10.0K  [0402]  21.28 103.74 270 top
R228  10.0K  [0402]  21.29 102.85 270 top
R229  10.0K  [0402]  21.29 101.96 270 top
R230  10.0K  [0402]  25.66 108.28 180 bottom
R231  10.0K  [0402]  21.28 104.73 270 top
R232  10.0K  [0402]  26.55 108.28 180 bottom
R233  10.0K  [0402]  23.63 92.03 0 bottom
R234  10.0K  [0402]  18.55 98.45 180 bottom
R235  10.0K  [0402]  33.28 108.28 180 bottom
R236  10.0K  [0402]  30.61 92.41 270 bottom
R238  0  [0402]  139.16 85.93 0 bottom
R239  0  [0402]  140.16 85.93 0 bottom
R241  1K  [0402]  46.11 19.26 0 top
R242  1K  [0402]  41.79 21.16 270 top
R243  4.7K  [0402]  54.24 24.72 180 bottom
R244  10.0K  [0402]  41.54 29.16 270 top
R245  10.0K  [0402]  41.54 30.05 270 top
R246  0  [0402]  55.51 23.07 270 top
R247  4.7K  [0402]  42.81 27.76 90 bottom
R248  0  [0402]  55.51 22.05 270 top
R249  0  [0402]  50.69 19.25 180 top
R250  0  [0402]  49.68 19.25 180 top
R251  0  [0402]  55.51 25.1 270 top
R252  0  [0402]  55.51 24.08 270 top
R253  0  [0402]  52.73 19.25 180 top
R254  0  [0402]  51.71 19.25 180 top
R255  0  [0402]  55.51 29.16 270 top
R256  0  [0402]  55.51 28.15 270 top
R257  0  [0402]  55.51 31.19 270 top
R258  0  [0402]  55.51 30.18 270 top
R259  0  [0402]  55.51 32.21 270 top
R260  1K  [0402]  207.4 105.23 270 top
R261  0  [0402]  209.3 106.76 270 bottom
R262  0  [0402]  207.4 104.35 90 top
R263  0  [0402]  209.3 107.65 270 bottom
R264  0  [0402]  207.4 103.46 90 top
R265  1K  [0402]  207.4 106.12 270 top
R266  DNI  [0402]  209.81 100.92 180 bottom
R267  1K  [0402]  207.4 102.57 270 top
R268  DNI  [0402]  207.4 101.68 270 top
R269  1K  [0402]  208.8 100.92 180 bottom
R270  22  [0402]  33.92 38.43 90 bottom
R271  4.7K  [0402]  41.66 46.56 90 bottom
R272  22  [0402]  33.92 39.32 90 bottom
R273  10.0K  [0402]  2.67 73.61 180 bottom
R274  1K  [0402]  14.23 75.39 180 bottom
R275  1K  [0402]  14.23 73.48 180 bottom
R276  1K  [0402]  14.23 71.58 180 bottom
R277  1K  [0402]  14.23 69.42 0 bottom
R278  10.0K  [0402]  2.67 71.71 180 bottom
R279  10.0K  [0402]  2.67 69.8 0 bottom
R280  4.7K  [0402]  27.06 47.7 90 bottom
R281  10.0K  [0402]  31.12 47.7 270 bottom
R282  4.7K  [0402]  27.06 48.59 90 bottom
R283  10.0K  [0402]  31.12 48.59 270 bottom
R284  DNI  [0402]  15.12 47.7 90 bottom
R285  DNI  [0402]  15.12 45.93 90 bottom
R286  4.7K  [0402]  15.12 46.81 90 bottom
R287  4.7K  [0402]  15.12 48.59 90 bottom
R288  0  [0402]  19.18 48.59 270 bottom
R289  0  [0402]  19.18 47.7 270 bottom
R290  10.0K  [0402]  2.67 63.83 0 bottom
R291  10.0K  [0402]  2.67 65.74 180 bottom
R292  10.0K  [0402]  2.67 67.64 180 bottom
R293  4.7K  [0402]  21.09 47.7 90 bottom
R294  4.7K  [0402]  21.09 48.59 90 bottom
R295  1K  [0402]  14.23 67.64 180 bottom
R296  0  [0402]  25.15 48.59 270 bottom
R297  1K  [0402]  14.23 65.74 180 bottom
R298  0  [0402]  25.15 47.7 270 bottom
R299  1K  [0402]  14.23 63.83 180 bottom
R300  1K  [0402]  14.23 61.93 0 bottom
R301  10.0K  [0402]  2.67 61.93 0 bottom
R302  4.7K  [0402]  87.13 93.68 90 bottom
R303  4.7K  [0402]  88.91 93.68 90 bottom
R304  0  [0402]  89.03 103.58 0 bottom
R305  0  [0402]  87.89 103.58 0 bottom
R306  56.2  [0402]  267.85 35.26 180 top
R307  1K  [0402]  269.37 36.4 270 bottom
R308  DNI  [0402]  269.37 37.29 270 bottom
R309  56.2  [0402]  269.37 38.31 90 bottom
R310  10.0K  [0402]  265.18 36.15 270 bottom
R311  56.2  [0402]  269.37 39.96 90 bottom
R312  49.9  [0402]  269.37 41.23 90 bottom
R313  10.0K  [0402]  264.42 64.47 180 bottom
R314  56.2  [0402]  269.37 42.62 90 bottom
R315  100K  [0402]  266.07 60.53 180 bottom
R316  56.2  [0402]  269.37 44.15 90 bottom
R317  56.2  [0402]  267.85 45.67 0 top
R318  10.0K  [0402]  28.67 17.62 90 bottom
R319  10.0K  [0402]  265.18 52.4 180 bottom
R320  10.0K  [0402]  265.18 56.47 180 bottom
R321  DNI  [0402]  267.22 51.51 0 bottom
R322  1K  [0402]  265.06 60.53 180 bottom
R323  1K  [0402]  264.17 56.47 180 bottom
R324  1K  [0402]  264.17 52.4 180 bottom
R325  DNI  [0402]  262.06 107.55 270 bottom
R326  0  [0402]  19.18 19.95 0 top
R327  DNI  [0402]  6.87 24.21 90 bottom
R328  100K  [0402]  10.29 31.14 90 bottom
R329  0  [0402]  2.01 18.37 180 bottom
R330  2K  [0402]  17.15 19.95 0 top
R331  2K  [0402]  18.17 19.95 0 top
R332  22  [0402]  16.14 19.95 180 top
R333  DNI  [0402]  31 29.72 180 bottom
R334  10.0K  [0402]  30.11 29.72 0 bottom
R335  10.0K  [0402]  38.43 20.02 0 bottom
R336  10.0K  [0402]  37.22 29.72 180 bottom
R337  10.0K  [0402]  37.31 26.42 180 bottom
R338  10.0K  [0402]  38.43 24.02 180 bottom
R339  10.0K,DNI  [0402]  8.64 29.77 180 bottom
R340  10.0K  [0402]  7.63 29.77 180 bottom
R341  1K  [0402]  227.61 107.43 180 bottom
R342  1K  [0402]  230.15 107.43 180 bottom
R343  1K  [0402]  232.69 107.43 180 bottom
R344  20.0K  [0402]  10.87 27.97 90 bottom
R345  1K  [0402]  224.82 107.43 0 bottom
R346  0  [0402]  223.8 107.43 0 bottom
R347  1K  [0402]  222.53 107.43 0 bottom
R348  1K  [0402]  2.8 42.75 180 bottom
R349  1K  [0402]  2.8 44.66 180 bottom
R350  1K  [0402]  2.8 46.56 180 bottom
R351  1K  [0402]  2.8 48.47 180 bottom
R352  1K  [0402]  38.43 26.42 0 bottom
R353  1K  [0402]  36.83 25.06 90 bottom
R354  0  [0402]  37.23 18.42 180 bottom
R355  1K  [0402]  38.43 28.42 180 bottom
R356  1K  [0402]  32.77 29.72 180 bottom
R357  0  [0402]  38.43 22.02 180 bottom
R358  10.0K,DNI  [0402]  34.55 29.72 0 bottom
R359  1K  [0402]  33.66 29.72 180 bottom
R360  10  [0402]  254.64 36.02 0 bottom
R361  49.9  [0402]  247.53 34.11 0 bottom
R362  10  [0402]  256.67 36.02 0 bottom
R363  49.9  [0402]  248.55 34.11 0 bottom
R364  49.9  [0402]  249.56 34.11 0 bottom
R365  49.9  [0402]  247.66 31.7 90 bottom
R367  49.9  [0402]  247.66 30.69 90 bottom
R368  49.9  [0402]  249.56 36.02 0 bottom
R369  10  [0402]  256.67 34.11 0 bottom
R370  49.9  [0402]  247.66 29.67 90 bottom
R371  49.9  [0402]  247.66 27.64 90 bottom
R372  10  [0402]  258.71 36.02 0 bottom
R373  49.9  [0402]  247.66 26.62 90 bottom
R374  49.9  [0402]  247.66 23.57 90 bottom
R375  10  [0402]  252.61 36.02 0 bottom
R376  10  [0402]  260.74 36.02 0 bottom
R377  49.9  [0402]  247.66 25.61 90 bottom
R378  49.9  [0402]  247.66 20.4 90 bottom
R379  49.9  [0402]  247.66 22.43 90 bottom
R380  49.9  [0402]  247.66 21.41 90 bottom
R381  10  [0402]  258.71 34.11 0 bottom
R382  49.9  [0402]  249.18 20.91 180 bottom
R383  10  [0402]  260.74 34.11 0 bottom
R384  10  [0402]  252.61 34.11 0 bottom
R385  DNI  [0402]  250.2 20.91 180 bottom
R386  10  [0402]  254.64 34.11 0 bottom
R387  0  [0402]  260.23 32.26 90 bottom
R390  10.0K  [0402]  260.23 28.27 90 bottom
R391  0  [0402]  250.58 34.11 0 bottom
R392  0  [0402]  250.58 36.02 0 bottom
R393  0  [0402]  260.23 31.32 270 bottom
R394  0  [0402]  260.23 25.22 270 bottom
R395  10.0K  [0402]  260.23 24.21 90 bottom
R396  10.0K  [0402]  260.23 23.19 90 bottom
R397  10.0K  [0402]  260.23 30.3 90 bottom
R398  10.0K  [0402]  260.23 27.26 90 bottom
R399  10.0K  [0402]  73.54 89.36 90 bottom
R400  10.0K  [0402]  71.57 88.47 90 bottom
R401  0  [0402]  70.05 80.09 0 top
R402  0  [0402]  70.94 80.09 0 top
R404  200K  [0402]  265.79 87.35 270 bottom
R405  100K,DNI  [0402]  245.46 99.6 0 bottom
R406  5.49M  [0402]  246.69 104.68 90 bottom
R407  10.0K  [0402]  246.37 99.6 0 bottom
R408  0  [0402]  244.56 99.6 180 bottom
R409  10  [0402]  247.05 90.25 270 top
R410  100K  [0402]  245.4 105.59 270 bottom
R411  100K  [0402]  245.07 80.37 270 bottom
R412  41.2K  [0402]  242.4 84.66 0 bottom
R413  200K  [0402]  244.91 104.68 90 bottom
R414  5.76K  [0402]  241.51 84.66 180 bottom
R415  240  [0402]  239.73 84.66 0 bottom
R416  1K  [0402]  244.15 83.7 90 bottom
R417  100K,DNI  [0402]  245.35 78.95 180 bottom
R418  5.49M  [0402]  248.47 82.2 90 bottom
R419  10.0K  [0402]  246.77 78.31 270 top
R420  0  [0402]  244.61 78.95 0 bottom
R421  100K  [0402]  246.69 82.2 270 bottom
R422  200K  [0402]  244.91 82.2 90 bottom
R423  10.0K  [0402]  259.21 54.94 0 bottom
R424  10.0K  [0402]  256.67 54.94 0 bottom
R425  200K  [0402]  258.2 59.39 0 top
R426  60.4K  [0402]  262.77 75.9 0 bottom
R427  1.91K  [0402]  257.69 57.99 90 top
R428  60.4K  [0402]  262.77 71.96 0 bottom
R429  20.0K  [0402]  262.77 73.87 180 bottom
R430  6.04K  [0402]  257.18 59.39 180 top
R431  100K  [0402]  244.04 50.24 180 bottom
R432  200K  [0402]  243.97 52.02 0 bottom
R433  10  [0402]  245.24 56.34 180 bottom
R434  100K,DNI  [0402]  243.14 49.69 0 bottom
R435  100K  [0402]  242.65 51.82 180 bottom
R436  100K  [0402]  243.85 55.2 90 bottom
R437  100K,DNI  [0402]  240.29 53.93 90 bottom
R438  100K,DNI  [0402]  244 56.59 0 bottom
R439  100K,DNI  [0402]  245.37 48.62 270 top
R440  100K  [0402]  240.44 56.49 0 bottom
R441  0  [0402]  243.34 53.93 90 bottom
R442  24.9K  [0402]  239.17 56.06 90 bottom
R443  8.25K  [0402]  242.58 49 90 top
R444  4.02K  [0402]  257.31 42.05 0 top
R445  2.61K  [0402]  26.76 37.91 270 bottom
R446  10.0K  [0402]  250.05 42.32 180 top
R447  10.0K  [0402]  25.53 43.89 90 bottom
R448  715  [0402]  256.39 42.94 180 top
R449  1K  [0402]  24.98 37.91 270 bottom
R470  0  [0402]  249.35 25.46 180 bottom
R471  0  [0402]  250.15 23.86 0 bottom
R514  0  [0402]  214.89 23.07 180 bottom
R515  0  [0402]  216.03 20.4 180 bottom
R516  0  [0402]  213.37 23.07 180 bottom
R546  4.02K  [0402]  206.16 51.81 180 top
R547  DNI  [0402]  212.45 51.03 0 bottom
R548  1.54K  [0402]  207.07 50.9 0 top
R549  4.7K  [0402]  210.99 50.48 270 bottom
R647  10.0K  [0402]  47.76 105.74 180 bottom
R648  10.0K,DNI  [0402]  47.73 103.84 180 bottom
R649  0  [0402]  48.62 103.84 0 bottom
R650  10.0K  [0402]  47.73 102.06 0 bottom
R651  10.0K  [0402]  54.87 108.16 270 bottom
R652  10.0K  [0402]  52.97 107.14 90 bottom
R653  10.0K  [0402]  210.5 19.55 0 bottom
R654  10.0K,DNI  [0402]  209.49 18.54 180 top
R655  0  [0402]  209.23 21.64 180 top
R656  10.0K  [0402]  209.42 20.06 90 top
R657  10.0K  [0402]  205.3 16.25 90 bottom
R658  10.0K  [0402]  206.18 17.27 270 bottom
R667  DNI  [1206]  41.16 70.56 270 bottom
R668  0  [0402]  35.06 71.96 0 bottom
R669  DNI  [0402]  31.5 68.91 90 bottom
R670  0  [0402]  31.5 68.02 90 bottom
R671  4.7K  [0402]  31.5 67.13 270 bottom
R672  10.0K  [0402]  104.52 83.98 180 bottom
R673  10.0K  [0402]  105.39 83.98 180 bottom
R674  10.0K  [0402]  129.64 39.87 0 bottom
R675  10.0K  [0402]  130.5 39.87 0 bottom
R676  10.0K  [0402]  128.77 39.87 0 bottom
R677  10.0K  [0402]  127.9 39.87 0 bottom
R678  0  [0402]  128.15 100.92 180 bottom
R679  0  [0402]  129.17 100.92 180 bottom
R680  2.61K  [0402]  18.5 37.91 270 bottom
R681  10.0K  [0402]  17.28 43.89 90 bottom
R682  1.87K  [0402]  16.72 37.91 270 bottom
R703  49.9  [0402]  248.55 36.02 0 bottom
R704  200  [0402]  2.45 58.37 0 bottom
R705  200  [0402]  6.97 52.66 180 bottom
R706  200  [0402]  6.08 52.66 180 bottom
R707  200  [0402]  10.58 59.64 0 bottom
R708  200  [0402]  15.96 52.66 180 bottom
R709  200  [0402]  15.07 52.66 180 bottom
R710  4.7K  [0402]  72.4 93.3 180 bottom
R711  4.7K  [0402]  73.67 93.3 180 bottom
R714  4.7K  [0402]  74.94 93.3 180 bottom
R715  4.7K,DNI  [0402]  72.4 103.08 270 bottom
R716  4.7K,DNI  [0402]  72.4 104.22 270 bottom
R717  4.7K,DNI  [0402]  74.56 103.58 180 bottom
R718  4.7K,DNI  [0402]  79.64 103.08 270 bottom
R719  4.7K,DNI  [0402]  81.16 103.58 180 bottom
R720  4.7K  [0402]  80.02 93.3 180 bottom
R721  4.7K,DNI  [0402]  82.18 103.58 180 bottom
R722  4.7K  [0402]  81.29 93.3 180 bottom
R723  4.7K  [0402]  82.56 93.3 180 bottom
R724  1M  [0402]  15.25 98.45 180 bottom
R729  10.0K  [0402]  74.49 88.47 270 bottom
R730  0  [0402]  71.95 80.09 0 top
R731  0  [0402]  72.84 80.09 0 top
R732  0  [0402]  73.86 80.09 0 top
R733  0  [0402]  74.75 80.09 0 top
R734  0  [0402]  75.76 80.09 0 top
R735  0  [0402]  76.65 80.09 0 top
R773  49.9  [0402]  58.17 11 180 top
R774  49.9  [0402]  65.92 11 0 bottom
R775  49.9  [0402]  73.67 11 180 top
R776  49.9  [0402]  78.75 11 0 bottom
R777  49.9  [0402]  80.65 11 0 bottom
R778  49.9  [0402]  124.59 11 180 top
R779  49.9  [0402]  96.65 11 0 bottom
R780  49.9  [0402]  60.59 11 180 top
R781  49.9  [0402]  80.78 11 180 top
R782  49.9  [0402]  96.65 11 180 top
R783  49.9  [0402]  120.78 11 180 top
R784  10.0K  [0402]  251.75 22.98 180 bottom
R785  10.0K  [0402]  255.4 43.49 180 bottom
R786  10.0K  [0402]  24.98 37.04 270 bottom
R787  10.0K  [0402]  16.72 37.04 270 bottom
R788  4.7K  [0402]  208.39 50.78 270 bottom
R789  10.0K  [0402]  119.69 96.95 180 bottom
R790  10.0K  [0402]  120.14 105.02 270 bottom
R791  10.0K  [0402]  138.79 26.42 90 bottom
R792  10.0K  [0402]  138.79 18.77 90 bottom
R793  100  [0402]  145.23 102.11 270 bottom
R794  100K  [0402]  40.03 19.62 90 bottom
R797  0  [0402]  198.76 106.25 180 bottom
R798  0  [0402]  199.78 106.25 180 bottom
R799  0  [0402]  202.32 106.25 180 bottom
R800  0  [0402]  203.33 106.25 180 bottom
R801  4.7K,DNI  [0402]  200.67 98.38 180 bottom
R802  1K  [0402]  198.89 98.38 180 bottom
R803  1K  [0402]  202.06 103.46 0 top
R804  1K  [0402]  199.78 98.38 180 bottom
R805  DNI  [0402]  205.29 98.02 180 bottom
R806  DNI  [0402]  204.45 98 180 bottom
R807  DNI  [0402]  202.95 98 180 bottom
R808  DNI  [0402]  201.94 98 180 bottom
R809  4.7K  [0402]  205.87 102.44 180 top
R810  DNI  [0402]  100.19 65.43 180 bottom
R811  DNI  [0402]  101.06 65.93 180 bottom
R812  DNI  [0402]  130.93 68.68 120 bottom
R813  DNI  [0402]  130.93 70.68 300 bottom
R814  1K  [0402]  202.32 28.08 0 bottom
R815  DNI  [0402]  240.29 63.32 90 top
R816  1K  [0402]  240.29 62.41 270 top
R817  DNI  [0402]  240.29 64.24 90 top
R818  1K  [0402]  240.29 65.15 270 top
R819  DNI  [0402]  240.29 66.98 90 top
R820  1K  [0402]  240.29 66.07 270 top
R821  DNI  [0402]  249.31 63.63 180 top
R822  1K  [0402]  250.58 63.58 180 top
R823  DNI  [0402]  253.35 28.74 0 bottom
R824  DNI  [0402]  199.78 107.14 0 bottom
R825  DNI  [0402]  198.76 107.14 0 bottom
R826  DNI  [0402]  203.33 107.14 0 bottom
R827  DNI  [0402]  202.32 107.14 0 bottom
R828  4.7K  [0402]  247.28 99.6 180 bottom
R829  4.7K  [0402]  250.37 78.6 180 bottom
R830  4.7K  [0402]  35.06 69.93 180 bottom
R831  10.0K,DNI  [0402]  34.93 45.8 0 bottom
R832  4.7K  [0402]  83.14 21.1 270 bottom
R833  4.7K  [0402]  83.57 30.56 180 bottom
R834  0  [0402]  41.54 31.07 90 top
R873  DNI  [RESC1005X40L20L]  217.84 19.28 0 bottom
R874  15K  [RESC1005X40L20L]  214.89 20.4 180 bottom
R875  15K  [RESC1005X40L20L]  216.03 23.07 180 bottom
R876  15K  [RESC1005X40L20L]  212.35 23.07 180 bottom
R877  15K  [RESC1005X40L20L]  218.57 25.99 90 bottom
R978  DNI  [0402]  212.72 93.3 270 bottom
R5757  10.0K  [0402]  105 65.15 60 bottom
R5758  10.0K  [0402]  103.66 65.48 180 bottom
R5772  DNI  [0402]  209.01 27.99 180 bottom
R5773  0  [0402]  136.79 36.27 180 bottom
R5774  10.0K  [0402]  132.37 40.31 0 bottom
R5776  100K  [R0402]  207.68 95.38 180 bottom
R5777  100K  [R0402]  208.4 97.06 90 bottom
R5780  0  [0402]  211.52 91.94 270 bottom
R5784  10  [0402]  156.73 81.36 0 bottom
R5785  143K,DNI  [R0402]  209.92 91.3 180 bottom
R5786  10  [0402]  157.61 81.36 0 bottom
R5787  43.2K  [R0402]  209.92 93.06 180 bottom
R5788  4.7K  [0402]  209.12 95.54 90 bottom
R5789  49.9  [0402]  247.53 36.02 0 bottom
R5928  499E  [0402]  194.55 63.78 270 bottom
R5929  10k  [0402]  195.71 57.64 270 bottom
R5930  499E  [0402]  197.62 66.14 90 top
R5931  10k  [0402]  203.51 58.93 180 top
R5932  499E  [0402]  194.56 64.69 270 bottom
R5933  10k  [0402]  195.64 58.63 270 bottom
R5934  499E  [0402]  195.92 66.07 90 top
R5935  10k  [0402]  195.43 59.87 0 top
R5936  10k  [0402]  194.19 60.51 90 bottom
R5937  10k  [0402]  195.97 55.81 270 top
R5938  10k  [0402]  195.97 54.89 270 top
R5939  18.7K  [0402]  200.13 54.97 180 top
R5940  5.11K  [0402]  201.15 55.17 180 top
R5941  3.09K  [0402]  202.17 55.22 180 top
R5942  6.49K  [0402]  203.84 55.12 270 top
R5943  0,DNI  [RESC1005X40L20L]  198.15 55.35 180 top
R5944  1E  [RESC1005X40L20L]  189.62 82.35 180 bottom
R5945  0  [RESC1005X40L20L]  190.56 80.44 0 bottom
R5946  0  [RESC1005X40L20L]  190.13 85.96 90 bottom
R5947  100  [RESC1005X40L20L]  190.79 64.7 270 bottom
R5948  100, DNI  [RESC1608X60L27N]  167.09 86.69 0 bottom
R5949  100  [RESC1005X40L20L]  197.14 65.28 90 bottom
R5951  0  [RESC1005X40L20L]  189.9 67.21 270 bottom
R5952  0  [RESC1005X40L20L]  190.1 73.84 90 bottom
R5954  0  [RESC1005X40L20L]  189.67 51.69 270 bottom
R5955  0  [RESC1005X40L20L]  189.64 59.46 180 bottom
R5956  0  [0402]  200.84 53.44 270 top
R5957  10.0K  [0402]  197.62 50.24 270 top
R5958  215K  [0402]  199.3 53.14 225 top
R5960  100K  [0402]  198.74 52.38 45 top
R5961  0  [RESC1005X40L20L]  190.1 35.82 270 bottom
R5962  0  [RESC1005X40L20L]  189.54 42.9 180 bottom
R5963  0  [0402]  226.72 56.42 180 bottom
R5964  DNI  [0402]  232.85 54.94 270 bottom
R5965  0,DNI  [0402]  230.26 59.01 180 bottom
R5966  0  [0402]  230.26 55.6 0 bottom
R5967  0  [0402]  230.26 57.31 0 bottom
R5968  10.0K  [0402]  229.04 53.01 180 bottom
R5969  10.0K,DNI  [0402]  227.74 50.52 180 bottom
R5970  10.0K  [0402]  233.33 52.4 270 bottom
R5971  10.0K  [0402]  229.55 48.59 90 bottom
R5972  10.0K  [0402]  228.68 49.56 315 bottom
R5973  DNI  [0402]  229.95 50.17 45 bottom
R5974  0  [0402]  227.74 52.43 0 bottom
R5975  10.0K  [0402]  234.45 51.13 270 bottom
R5976  DNI  [0402]  227.13 54.94 90 bottom
R5977  0  [0402]  229.93 51.49 225 bottom
R5978  4.7K  [0402]  230.26 53.09 180 bottom
R5980  787E  [0402]  231.25 48.59 270 bottom
R5981  10.7K  [0402]  234.02 49.38 180 bottom
R5982  2.61K  [0402]  232.39 51.13 90 bottom
R5983  16.2K  [0402]  232.42 49.89 90 bottom
R5984  100K  [R0402]  208.64 56.57 180 bottom
R5985  100K,DNI  [0402]  212.48 60.15 90 bottom
R5986  100K,DNI  [R0402]  207.37 56.7 180 bottom
R5987  100K  [R0402]  209.91 59.77 0 bottom
R5988  DNI  [0402]  207.58 61.8 90 bottom
R5989  DNI  [0402]  205.09 58.35 0 bottom
R5990  0  [0402]  204.17 58.35 0 bottom
R5991  4.7K  [0402]  206 58.35 180 bottom
R5992  1.2K  [0402]  207.32 54.92 270 bottom
R5993  180K  [0402]  205.47 54.74 270 bottom
R5994  100K  [0402]  70.95 70.44 0 bottom
R5995  DNI  [0402]  65.03 71.96 0 bottom
R5996  19.1K  [0402]  70.48 72.19 270 bottom
R5997  0  [0402]  64.14 71.96 0 bottom
R5998  4.7K  [0402]  63.33 73.92 0 bottom
R5999  0  [0402]  67.72 68.51 180 bottom
R6000  49.9K  [0402]  72.8 69.01 270 bottom
R6001  49.9K  [0402]  70.64 67.74 270 bottom
R6002  0  [0402]  233.56 76.28 270 bottom
R6003  0  [0402]  233.56 75.01 270 bottom
R6004  10.0K,DNI  [0402]  219.02 74.42 270 bottom
R6005  1.65K  [0402]  217.74 70.59 270 bottom
R6006  0  [0402]  220.28 75.09 180 bottom
R6007  0  [0402]  232.8 68.66 90 bottom
R6008  0.005 OHM  [RES_CSNL2512_0_005-0_006]  236.99 74.63 270 top
R6011  DNI  [0402]  219.01 72.8 0 bottom
R6012  10.0K  [0402]  222.5 69.01 315 bottom
R6013  825E  [0402]  220.3 70.79 0 bottom
R6014  0  [0402]  219.03 70.67 0 bottom
R6015  DNI  [0402]  219.01 67.11 0 bottom
R6016  4.7K  [0402]  217.84 72.49 270 bottom
R6017  0  [0402]  224.06 71.25 90 bottom
R6018  10.0K  [0402]  220.25 72.8 180 bottom
R6019  10.0K  [0402]  217.63 75.01 180 bottom
R6020  10.0K  [0402]  220 68.99 135 bottom
R6021  10.0K  [0402]  217.94 76.3 270 bottom
R6022  22.6K  [0402]  222.18 70.54 180 bottom
R6023  10.0K  [0402]  220.2 67.08 180 bottom
R6024  100K  [0402]  70.9 56.54 0 bottom
R6026  10.0K  [0402]  70.49 58.37 270 bottom
R6027  0  [0402]  64.12 58.3 0 bottom
R6028  4.7K  [0402]  63.89 60.07 0 bottom
R6029  0  [0402]  67.72 54.71 180 bottom
R6030  49.9K  [0402]  72.75 55.17 270 bottom
R6031  49.9K  [0402]  71.46 53.9 270 bottom
R6032  DNI  [0402]  203.23 87.23 90 bottom
R6033  0  [0402]  203.99 88.45 0 bottom
R6034  4.7K  [0402]  205.24 86.57 0 bottom
R6035  15K  [0402]  200.79 88.22 180 bottom
R6036  0  [0402]  202.19 88.72 270 bottom
R6037  10.0K  [0402]  203.16 83.24 90 bottom
R6038  100K  [R0402]  199.24 86.31 90 bottom
R6039  DNI  [0402]  210.56 46.69 0 bottom
R6040  0  [0402]  211.46 46.69 0 bottom
R6041  4.7K  [0402]  205.5 46.56 0 bottom
R6042  15K  [0402]  207.31 46.56 180 bottom
R6043  0  [0402]  208.22 46.56 180 bottom
R6044  100K  [R0402]  204.59 46.56 0 bottom
R6045  10.0K  [0402]  203.66 46.56 0 bottom
R6055  100K  [R0402]  211.59 65.51 0 top
R6056  100K,DNI  [0402]  214.51 67.39 270 top
R6057  100K,DNI  [R0402]  213.24 67.52 0 top
R6058  100K  [R0402]  212.25 70.23 315 top
R6059  DNI  [0402]  214.54 70.61 90 top
R6060  DNI  [0402]  215.86 70.84 180 top
R6061  0  [0402]  215.83 69.14 0 top
R6062  4.7K  [0402]  214.48 69.34 90 top
R6063  19.1K  [0402]  213.88 65.23 180 top
R6065  100K  [R0402]  54.11 55.86 270 top
R6066  100K  [R0402]  55.73 56.26 315 top
R6067  72.3K  [0402]  58.68 57.11 180 bottom
R6071  100K  [R0402]  71.96 39.14 270 bottom
R6072  100K  [R0402]  73.9 39.25 0 bottom
R6073  100K  [R0402]  69.07 38.74 180 bottom
R6074  30.1K  [0402]  65.44 39.04 270 bottom
R6075  DNI  [0402]  73.68 36.78 90 top
R6076  0  [0402]  73.68 38.6 90 top
R6077  4.7K  [0402]  73.68 37.68 270 top
R6078  4.12K  [0402]  202.57 52.78 90 top
R6079  100K  [R0402]  54.98 51.77 270 bottom
R6083  DNI  [0402]  57.74 54.43 180 top
R6084  0  [0402]  58.88 54.92 270 bottom
R6085  4.7K  [0402]  55.65 54.75 225 top
R6086  6.49K  [0402]  203.84 56.14 270 top
R6087  1E  [RESC1005X40L20L]  189.72 69.93 180 bottom
R6088  1E  [RESC1005X40L20L]  189.54 54.89 180 bottom
R6089  1E  [RESC1005X40L20L]  189.52 38.61 180 bottom
